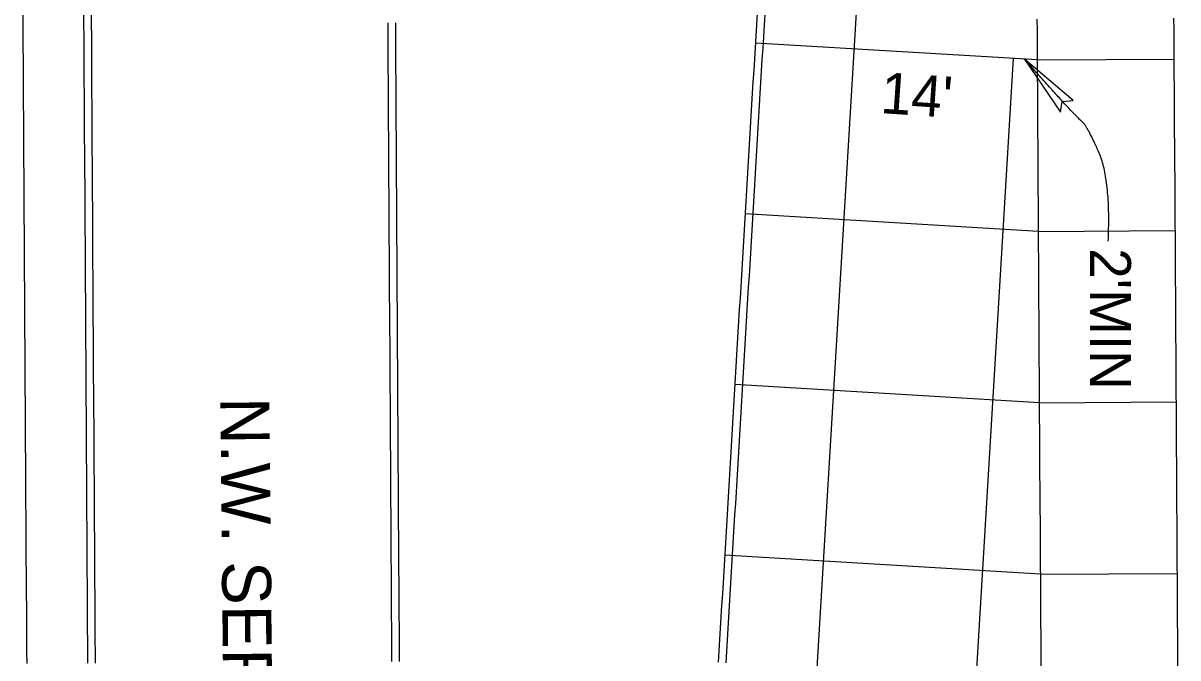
# Model space of a CAD drawing. Extents: x 2145147 to 2158018, y 137519 to 148068.
# Drawn here: x 2150664.6 to 2150765.9, y 144951.8 to 145007.5 of the extents above; entities that cross this region are included whole.
import ezdxf

# ---------------------------------------------------------------- set-up
doc = ezdxf.new("R2010")
doc.units = 0
for name, color, linetype in [('PR_Align_Service_C_Label', 7, 'Continuous'), ('PR_Dimensions', 7, 'Continuous'), ('PR_Joint_Contraction', 7, 'Continuous'), ('PR_Joint_Long', 7, 'Continuous'), ('PR_Phasing_Pavement_1', 7, 'Continuous'), ('PR_Road_Concrete', 7, 'Continuous')]:
    doc.layers.add(name, color=color, linetype=linetype)

msp = doc.modelspace()

# ---------------------------------------------------------------- linework, layer by layer
at = {"layer": 'PR_Dimensions'}
msp.add_lwpolyline([(2150752.47, 145004.3), (2150755.62, 144999.66), (2150755.79, 145000.59), (2150756.75, 145000.68)], close=True, dxfattribs=at)
msp.add_open_spline([(2150759.82, 144988.35), (2150760.06, 144993.69), (2150757.96, 144998.5), (2150757.02, 144999.21), (2150752.47, 145004.3)], degree=2, dxfattribs=at)
at = {"layer": 'PR_Joint_Contraction'}
for p, q in [((2150753.61, 145004.23), (2150728.85, 145005.72)), ((2150753.61, 145004.23), (2150765.61, 145004.31)), ((2150753.7, 144989.2), (2150727.95, 144990.75)), ((2150753.7, 144989.2), (2150765.7, 144989.27)), ((2150753.79, 144974.17), (2150727.05, 144975.77)), ((2150753.79, 144974.17), (2150765.79, 144974.24)), ((2150753.88, 144959.14), (2150726.15, 144960.8)), ((2150753.88, 144959.14), (2150765.88, 144959.21))]:
    msp.add_line(p, q, dxfattribs=at)
at = {"layer": 'PR_Joint_Long'}
for points in [[(2150750.33, 145218.94), (2150715.84, 144644.41)], [(2150753.93, 144950.82), (2150753.93, 144951.82), (2150753.92, 144952.82), (2150753.92, 144953.82), (2150753.91, 144954.82), (2150753.9, 144955.82), (2150753.9, 144956.82), (2150753.89, 144957.82), (2150753.89, 144958.82), (2150753.88, 144959.82), (2150753.87, 144960.82), (2150753.87, 144961.82), (2150753.86, 144962.82), (2150753.86, 144963.82), (2150753.85, 144964.82), (2150753.84, 144965.82), (2150753.84, 144966.82), (2150753.83, 144967.82), (2150753.83, 144968.82), (2150753.82, 144969.82), (2150753.81, 144970.82), (2150753.81, 144971.82), (2150753.8, 144972.82), (2150753.8, 144973.82), (2150753.79, 144974.82), (2150753.78, 144975.82), (2150753.78, 144976.82), (2150753.77, 144977.82), (2150753.77, 144978.82), (2150753.76, 144979.82), (2150753.75, 144980.82), (2150753.75, 144981.82), (2150753.74, 144982.82), (2150753.74, 144983.82), (2150753.73, 144984.82), (2150753.72, 144985.82), (2150753.72, 144986.82), (2150753.71, 144987.82), (2150753.71, 144988.82), (2150753.7, 144989.82), (2150753.69, 144990.82), (2150753.69, 144991.82), (2150753.68, 144992.82), (2150753.68, 144993.82), (2150753.67, 144994.82), (2150753.67, 144995.23), (2150753.66, 144995.82), (2150753.66, 144996.82), (2150753.65, 144997.82), (2150753.65, 144998.82), (2150753.64, 144999.82), (2150753.63, 145000.82), (2150753.63, 145001.82), (2150753.62, 145002.82), (2150753.62, 145003.12), (2150753.62, 145003.82), (2150753.61, 145004.82), (2150753.6, 145005.82), (2150753.6, 145006.82), (2150753.59, 145007.82)], [(2150765.93, 144950.89), (2150765.93, 144951.89), (2150765.92, 144952.89), (2150765.92, 144953.89), (2150765.91, 144954.89), (2150765.9, 144955.89), (2150765.9, 144956.89), (2150765.89, 144957.89), (2150765.89, 144958.89), (2150765.88, 144959.89), (2150765.87, 144960.89), (2150765.87, 144961.89), (2150765.86, 144962.89), (2150765.86, 144963.89), (2150765.85, 144964.89), (2150765.84, 144965.89), (2150765.84, 144966.89), (2150765.83, 144967.89), (2150765.83, 144968.89), (2150765.82, 144969.89), (2150765.81, 144970.89), (2150765.81, 144971.89), (2150765.8, 144972.89), (2150765.8, 144973.89), (2150765.79, 144974.89), (2150765.78, 144975.89), (2150765.78, 144976.89), (2150765.77, 144977.89), (2150765.77, 144978.89), (2150765.76, 144979.89), (2150765.75, 144980.89), (2150765.75, 144981.89), (2150765.74, 144982.89), (2150765.74, 144983.89), (2150765.73, 144984.89), (2150765.72, 144985.89), (2150765.72, 144986.89), (2150765.71, 144987.89), (2150765.71, 144988.89), (2150765.7, 144989.89), (2150765.69, 144990.89), (2150765.69, 144991.89), (2150765.68, 144992.89), (2150765.68, 144993.89), (2150765.67, 144994.89), (2150765.67, 144995.3), (2150765.66, 144995.89), (2150765.66, 144996.89), (2150765.65, 144997.89), (2150765.65, 144998.89), (2150765.64, 144999.89), (2150765.63, 145000.89), (2150765.63, 145001.89), (2150765.62, 145002.89), (2150765.62, 145003.2), (2150765.62, 145003.89), (2150765.61, 145004.89), (2150765.6, 145005.89), (2150765.6, 145006.89), (2150765.59, 145007.89)], [(2150751.47, 145004.36), (2150729.81, 144643.57)]]:
    msp.add_lwpolyline(points, dxfattribs=at)
at = {"layer": 'PR_Phasing_Pavement_1'}
for points in [[(2150670.26, 144951.32), (2150670.25, 144952.32), (2150670.25, 144953.32), (2150670.24, 144954.32), (2150670.23, 144955.32), (2150670.23, 144956.32), (2150670.22, 144957.32), (2150670.22, 144958.32), (2150670.21, 144959.32), (2150670.2, 144960.32), (2150670.2, 144961.24), (2150670.2, 144961.25), (2150670.2, 144961.32), (2150670.19, 144962.32), (2150670.19, 144963.32), (2150670.18, 144964.32), (2150670.17, 144965.32), (2150670.17, 144966.32), (2150670.16, 144967.32), (2150670.16, 144968.32), (2150670.15, 144969.32), (2150670.14, 144970.32), (2150670.14, 144971.32), (2150670.13, 144972.32), (2150670.13, 144973.32), (2150670.12, 144974.32), (2150670.11, 144975.32), (2150670.11, 144976.32), (2150670.1, 144977.32), (2150670.1, 144978.32), (2150670.09, 144979.32), (2150670.08, 144980.32), (2150670.08, 144981.32), (2150670.07, 144982.32), (2150670.07, 144983.32), (2150670.06, 144984.32), (2150670.05, 144985.32), (2150670.05, 144986.32), (2150670.04, 144987.32), (2150670.04, 144988.32), (2150670.03, 144989.32), (2150670.02, 144990.32), (2150670.02, 144991.32), (2150670.01, 144992.32), (2150670.01, 144993.32), (2150670, 144994.32), (2150669.99, 144995.32), (2150669.99, 144996.32), (2150669.98, 144997.32), (2150669.98, 144998.32), (2150669.97, 144999.32), (2150669.96, 145000.32), (2150669.96, 145001.32), (2150669.95, 145002.32), (2150669.95, 145003.32), (2150669.94, 145004.32), (2150669.93, 145005.32), (2150669.93, 145006.32), (2150669.92, 145007.32), (2150669.92, 145008.32)], [(2150670.93, 144951.33), (2150670.92, 144952.33), (2150670.91, 144953.33), (2150670.91, 144954.33), (2150670.9, 144955.33), (2150670.9, 144956.33), (2150670.89, 144957.33), (2150670.88, 144958.33), (2150670.88, 144959.33), (2150670.87, 144960.33), (2150670.87, 144961.25), (2150670.87, 144961.25), (2150670.87, 144961.33), (2150670.86, 144962.33), (2150670.85, 144963.33), (2150670.85, 144964.33), (2150670.84, 144965.33), (2150670.84, 144966.33), (2150670.83, 144967.33), (2150670.82, 144968.33), (2150670.82, 144969.33), (2150670.81, 144970.33), (2150670.81, 144971.33), (2150670.8, 144972.33), (2150670.79, 144973.33), (2150670.79, 144974.33), (2150670.78, 144975.33), (2150670.77, 144976.33), (2150670.77, 144977.33), (2150670.76, 144978.33), (2150670.76, 144979.33), (2150670.75, 144980.33), (2150670.74, 144981.33), (2150670.74, 144982.33), (2150670.73, 144983.33), (2150670.73, 144984.33), (2150670.72, 144985.33), (2150670.71, 144986.33), (2150670.71, 144987.33), (2150670.7, 144988.33), (2150670.7, 144989.33), (2150670.69, 144990.33), (2150670.69, 144991.33), (2150670.68, 144992.33), (2150670.67, 144993.33), (2150670.67, 144994.33), (2150670.66, 144995.33), (2150670.65, 144996.33), (2150670.65, 144997.33), (2150670.64, 144998.33), (2150670.64, 144999.33), (2150670.63, 145000.33), (2150670.62, 145001.33), (2150670.62, 145002.33), (2150670.61, 145003.33), (2150670.61, 145004.33), (2150670.6, 145005.33), (2150670.6, 145006.33), (2150670.59, 145007.33), (2150670.58, 145008.33)], [(2150664.92, 144951.29), (2150664.91, 144952.29), (2150664.91, 144953.29), (2150664.9, 144954.29), (2150664.89, 144955.29), (2150664.89, 144956.29), (2150664.88, 144957.29), (2150664.88, 144958.29), (2150664.87, 144959.29), (2150664.86, 144960.29), (2150664.86, 144961.21), (2150664.86, 144961.22), (2150664.86, 144961.29), (2150664.85, 144962.29), (2150664.85, 144963.29), (2150664.84, 144964.29), (2150664.83, 144965.29), (2150664.83, 144966.29), (2150664.82, 144967.29), (2150664.82, 144968.29), (2150664.81, 144969.29), (2150664.8, 144970.29), (2150664.8, 144971.29), (2150664.79, 144972.29), (2150664.79, 144973.29), (2150664.78, 144974.29), (2150664.77, 144975.29), (2150664.77, 144976.29), (2150664.76, 144977.29), (2150664.76, 144978.29), (2150664.75, 144979.29), (2150664.74, 144980.29), (2150664.74, 144981.29), (2150664.73, 144982.29), (2150664.73, 144983.29), (2150664.72, 144984.29), (2150664.71, 144985.29), (2150664.71, 144986.29), (2150664.7, 144987.29), (2150664.7, 144988.29), (2150664.69, 144989.29), (2150664.68, 144990.29), (2150664.68, 144991.29), (2150664.67, 144992.29), (2150664.67, 144993.29), (2150664.66, 144994.29), (2150664.65, 144995.29), (2150664.65, 144996.29), (2150664.64, 144997.29), (2150664.64, 144998.29), (2150664.63, 144999.29), (2150664.62, 145000.29), (2150664.62, 145001.29), (2150664.61, 145002.29), (2150664.61, 145003.29), (2150664.6, 145004.29), (2150664.59, 145005.29), (2150664.59, 145006.29), (2150664.58, 145007.29), (2150664.58, 145008.29)], [(2150696.94, 144951.48), (2150696.94, 144952.48), (2150696.93, 144953.48), (2150696.93, 144954.48), (2150696.92, 144955.48), (2150696.92, 144956.48), (2150696.91, 144957.48), (2150696.9, 144958.48), (2150696.9, 144959.48), (2150696.89, 144960.48), (2150696.89, 144961.4), (2150696.89, 144961.41), (2150696.88, 144961.48), (2150696.88, 144962.48), (2150696.87, 144963.48), (2150696.87, 144964.48), (2150696.86, 144965.48), (2150696.85, 144966.48), (2150696.85, 144967.48), (2150696.84, 144968.48), (2150696.84, 144969.48), (2150696.83, 144970.48), (2150696.82, 144971.48), (2150696.82, 144972.48), (2150696.81, 144973.48), (2150696.81, 144974.48), (2150696.8, 144975.48), (2150696.79, 144976.48), (2150696.79, 144977.48), (2150696.78, 144978.48), (2150696.78, 144979.48), (2150696.77, 144980.48), (2150696.76, 144981.48), (2150696.76, 144982.48), (2150696.75, 144983.48), (2150696.75, 144984.48), (2150696.74, 144985.48), (2150696.73, 144986.48), (2150696.73, 144987.48), (2150696.72, 144988.48), (2150696.72, 144989.48), (2150696.71, 144990.48), (2150696.71, 144991.48), (2150696.7, 144992.48), (2150696.69, 144993.48), (2150696.69, 144994.48), (2150696.68, 144995.48), (2150696.67, 144996.48), (2150696.67, 144997.48), (2150696.66, 144998.48), (2150696.66, 144999.48), (2150696.65, 145000.48), (2150696.65, 145001.48), (2150696.64, 145002.48), (2150696.63, 145003.48), (2150696.63, 145004.48), (2150696.62, 145005.48), (2150696.62, 145006.48), (2150696.61, 145007.48)], [(2150697.61, 144951.49), (2150697.61, 144952.49), (2150697.6, 144953.49), (2150697.6, 144954.49), (2150697.59, 144955.49), (2150697.58, 144956.49), (2150697.58, 144957.49), (2150697.57, 144958.49), (2150697.56, 144959.49), (2150697.56, 144960.49), (2150697.55, 144961.41), (2150697.55, 144961.41), (2150697.55, 144961.49), (2150697.55, 144962.49), (2150697.54, 144963.49), (2150697.53, 144964.49), (2150697.53, 144965.49), (2150697.52, 144966.49), (2150697.52, 144967.49), (2150697.51, 144968.49), (2150697.5, 144969.49), (2150697.5, 144970.49), (2150697.49, 144971.49), (2150697.49, 144972.49), (2150697.48, 144973.49), (2150697.47, 144974.49), (2150697.47, 144975.49), (2150697.46, 144976.49), (2150697.46, 144977.49), (2150697.45, 144978.49), (2150697.44, 144979.49), (2150697.44, 144980.49), (2150697.43, 144981.49), (2150697.43, 144982.49), (2150697.42, 144983.49), (2150697.42, 144984.49), (2150697.41, 144985.49), (2150697.4, 144986.49), (2150697.4, 144987.49), (2150697.39, 144988.49), (2150697.38, 144989.49), (2150697.38, 144990.49), (2150697.37, 144991.49), (2150697.37, 144992.49), (2150697.36, 144993.49), (2150697.35, 144994.49), (2150697.35, 144995.49), (2150697.34, 144996.49), (2150697.34, 144997.49), (2150697.33, 144998.49), (2150697.32, 144999.49), (2150697.32, 145000.49), (2150697.31, 145001.49), (2150697.31, 145002.49), (2150697.3, 145003.49), (2150697.29, 145004.49), (2150697.29, 145005.49), (2150697.28, 145006.49), (2150697.28, 145007.49)]]:
    msp.add_lwpolyline(points, dxfattribs=at)
at = {"layer": 'PR_Road_Concrete'}
for points in [[(2150729, 145008.3), (2150728.94, 145007.31), (2150728.88, 145006.31), (2150728.82, 145005.31), (2150728.76, 145004.31), (2150728.7, 145003.31), (2150728.64, 145002.31), (2150728.58, 145001.32), (2150728.52, 145000.32), (2150728.46, 144999.32), (2150728.4, 144998.32), (2150728.34, 144997.32), (2150728.28, 144996.33), (2150728.22, 144995.33), (2150728.16, 144994.33), (2150728.1, 144993.33), (2150728.04, 144992.33), (2150727.98, 144991.33), (2150727.92, 144990.34), (2150727.86, 144989.34), (2150727.8, 144988.34), (2150727.74, 144987.34), (2150727.68, 144986.34), (2150727.62, 144985.35), (2150727.56, 144984.35), (2150727.5, 144983.35), (2150727.44, 144982.35), (2150727.38, 144981.35), (2150727.32, 144980.35), (2150727.26, 144979.36), (2150727.2, 144978.36), (2150727.14, 144977.36), (2150727.08, 144976.36), (2150727.02, 144975.36), (2150726.96, 144974.37), (2150726.9, 144973.37), (2150726.84, 144972.37), (2150726.78, 144971.37), (2150726.72, 144970.37), (2150726.66, 144969.37), (2150726.6, 144968.38), (2150726.54, 144967.38), (2150726.48, 144966.38), (2150726.42, 144965.38), (2150726.36, 144964.38), (2150726.31, 144963.38), (2150726.25, 144962.39), (2150726.19, 144961.39), (2150726.13, 144960.39), (2150726.07, 144959.39), (2150726.01, 144958.39), (2150725.95, 144957.4), (2150725.89, 144956.4), (2150725.83, 144955.4), (2150725.77, 144954.4), (2150725.71, 144953.4), (2150725.65, 144952.4), (2150725.59, 144951.41)], [(2150729.67, 145008.26), (2150729.61, 145007.27), (2150729.55, 145006.27), (2150729.49, 145005.27), (2150729.43, 145004.27), (2150729.37, 145003.27), (2150729.31, 145002.27), (2150729.25, 145001.28), (2150729.19, 145000.28), (2150729.13, 144999.28), (2150729.07, 144998.28), (2150729.01, 144997.28), (2150728.95, 144996.29), (2150728.89, 144995.29), (2150728.83, 144994.29), (2150728.77, 144993.29), (2150728.71, 144992.29), (2150728.65, 144991.29), (2150728.59, 144990.3), (2150728.53, 144989.3), (2150728.47, 144988.3), (2150728.41, 144987.3), (2150728.35, 144986.3), (2150728.29, 144985.31), (2150728.23, 144984.31), (2150728.17, 144983.31), (2150728.11, 144982.31), (2150728.05, 144981.31), (2150727.99, 144980.31), (2150727.93, 144979.32), (2150727.87, 144978.32), (2150727.81, 144977.32), (2150727.75, 144976.32), (2150727.69, 144975.32), (2150727.63, 144974.33), (2150727.57, 144973.33), (2150727.51, 144972.33), (2150727.45, 144971.33), (2150727.39, 144970.33), (2150727.33, 144969.33), (2150727.27, 144968.34), (2150727.21, 144967.34), (2150727.15, 144966.34), (2150727.09, 144965.34), (2150727.03, 144964.34), (2150726.97, 144963.34), (2150726.91, 144962.35), (2150726.85, 144961.35), (2150726.79, 144960.35), (2150726.73, 144959.35), (2150726.67, 144958.35), (2150726.61, 144957.36), (2150726.55, 144956.36), (2150726.49, 144955.36), (2150726.43, 144954.36), (2150726.37, 144953.36), (2150726.31, 144952.36), (2150726.25, 144951.37)]]:
    msp.add_lwpolyline(points, dxfattribs=at)

# ---------------------------------------------------------------- texts
at = {"layer": 'PR_Align_Service_C_Label'}
msp.add_text('N.W. SERV. RD.', height=4.3, rotation=270.5432, dxfattribs=at).set_placement((2150681.89, 144974.64))
at = {"layer": 'PR_Dimensions'}
for s, rotation, p in [("14'", 356.1069, (2150739.77, 144999.58)), ("2'MIN", 269.9996, (2150758.21, 144987.73))]:
    msp.add_text(s, height=3.6, rotation=rotation, dxfattribs=at).set_placement(p)

doc.saveas('drawing.dxf')
